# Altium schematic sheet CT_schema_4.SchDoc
size 297 x 173 mm
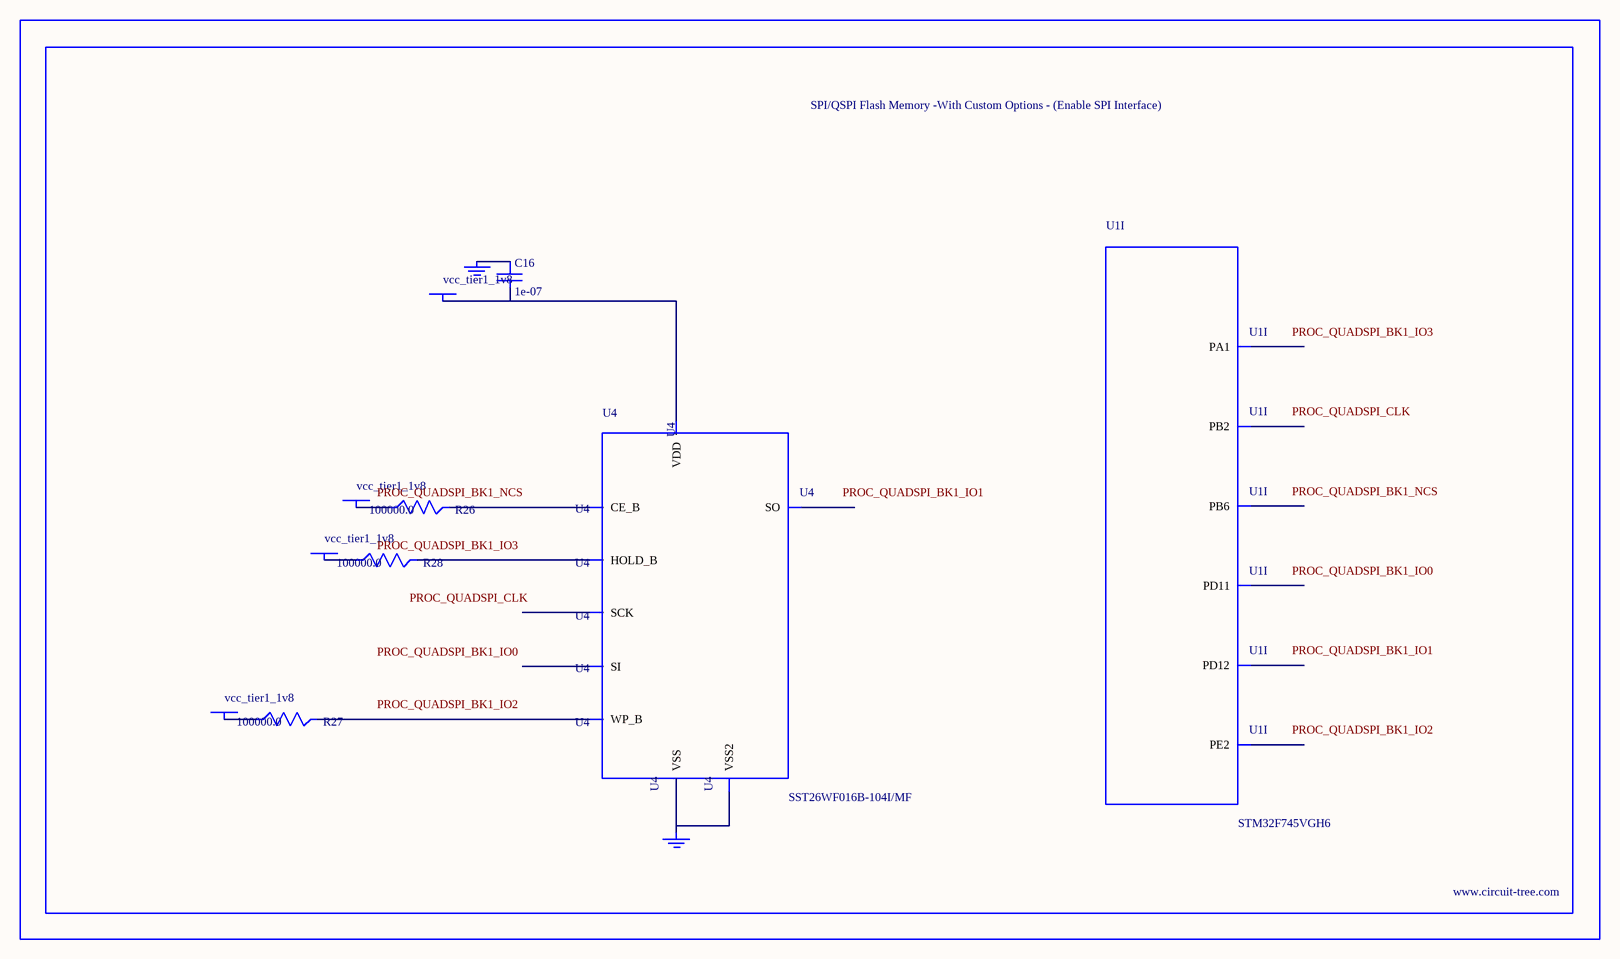
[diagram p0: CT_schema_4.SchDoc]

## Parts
BORDER3  (no value)
C16  1e-07  [C0402]
GND_INSTANCE_3_0  (no value)
GND_INSTANCE_3_1  (no value)
POWER_INSTANCE_3_0  vcc_tier1_1v8
POWER_INSTANCE_3_1  vcc_tier1_1v8
POWER_INSTANCE_3_2  vcc_tier1_1v8
POWER_INSTANCE_3_3  vcc_tier1_1v8
R26  100000.0  [R0603]
R27  100000.0  [R0603]
R28  100000.0  [R0603]
U1  STM32F745VGH6  [TFBGA100]  (part I of 9)
U4  SST26WF016B-104I/MF  [WFDN-8]

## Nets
NetC16_1: C16.1 GND_INSTANCE_3_0.0(GND)
NetC16_2: C16.2 POWER_INSTANCE_3_3.0(PWR) U4.8(VDD)
NetGND_INSTANCE_3_1_0: GND_INSTANCE_3_1.0(GND) U4.4(VSS) U4.9(VSS2)
NetPOWER_INSTANCE_3_0_0: POWER_INSTANCE_3_0.0(PWR) R26.1
NetPOWER_INSTANCE_3_1_0: POWER_INSTANCE_3_1.0(PWR) R27.1
NetPOWER_INSTANCE_3_2_0: POWER_INSTANCE_3_2.0(PWR) R28.1
NetR26_2: R26.2 U4.1(CE_B)
NetR27_2: R27.2 U4.3(WP_B)
NetR28_2: R28.2 U4.7(HOLD_B)

Not connected (* = marked no-connect by the designer): U1 A3(PE2) B5(PB6) G5(PB2) G9(PD11) H2(PA1) K10(PD12); U4 2(SO) 5(SI) 6(SCK)

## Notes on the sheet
- Labels drawn without touching a wire or pin: PROC_QUADSPI_BK1_IO0, PROC_QUADSPI_BK1_IO1, PROC_QUADSPI_BK1_IO2, PROC_QUADSPI_BK1_IO3, PROC_QUADSPI_BK1_NCS, PROC_QUADSPI_CLK

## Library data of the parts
BORDER3 = BORDER_PAGE3
C16 = C0402C104K3RACTU
GND_INSTANCE_3_0 GND_INSTANCE_3_1 = GND
POWER_INSTANCE_3_0-POWER_INSTANCE_3_3 = PWR
R26-R28 = RC0603JR-07100KL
